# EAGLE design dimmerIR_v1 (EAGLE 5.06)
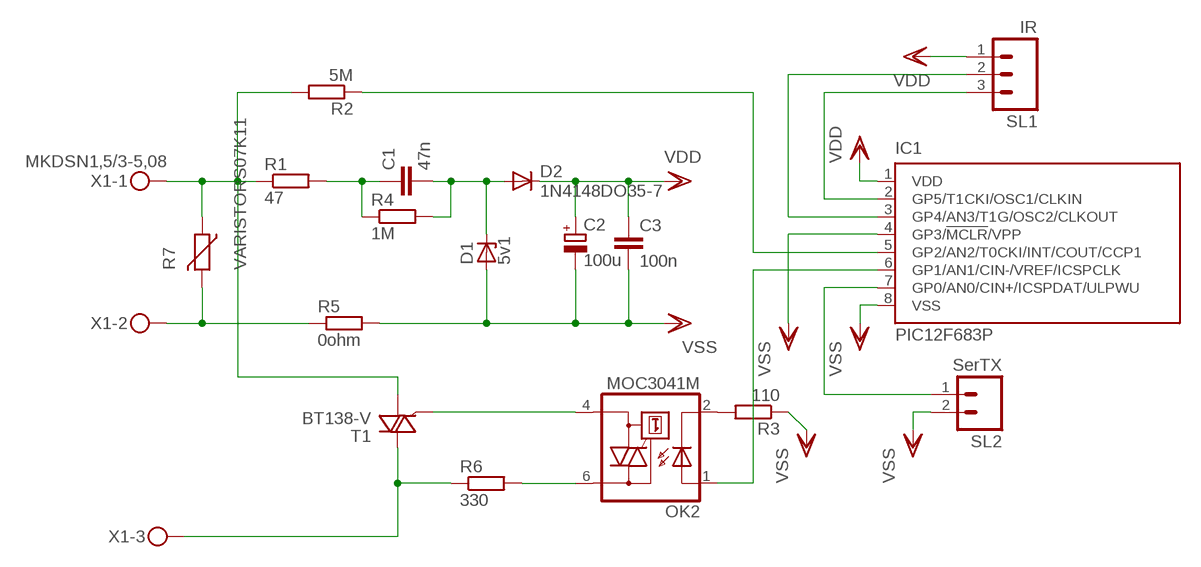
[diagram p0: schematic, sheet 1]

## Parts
C1  47n  C-EU150-054X183  [C150-054X183]
C2  100u  CPOL-EUE2.5-6  [E2,5-6]
C3  100n  C-EU050-025X075  [C050-025X075]
D1  5v1  ZENER-DIODEDO34-7  [DO34Z7]
D2  1N4148DO35-7  [DO35-7]
IC1  PIC12F683P  [DIL8]
OK2  MOC3041M  [DIL06]
R1  47  R-EU_0204/7  [0204/7]
R2  5M  R-EU_0207/10  [0207/10]
R3  110  R-EU_0207/10  [0207/10]
R4  1M  R-EU_M1206  [M1206]
R5  0ohm  R-EU_M1206  [M1206]
R6  330  R-EU_0207/10  [0207/10]
R7  VARISTORS07K11  [S07K11]
SL1  IR  M03  [03P]
SL2  SerTX  M02  [02P]
T1  BT138-V  [TO220BV]
X1  MKDSN1,5/3-5,08  [MKDSN1,5/3-5,08]

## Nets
N$1: R1.1 R2.2 R7.1 T1.T1(A1) X1.1
N$2: C1.2 D1.C D2.A R4.2
N$3: C1.1 R1.2 R4.1
N$4: R6.1 T1.T2(A2) X1.3
N$5: OK2.6(A2) R6.2
N$6: OK2.4(A1) T1.G
N$7: IC1.5(GP2/AN2/T0CKI/INT/COUT/CCP1) R2.1
N$8: IC1.6(GP1/AN1/CIN-/VREF/ICSPCLK) OK2.1(A)
N$9: OK2.2(C) R3.2
N$10: IC1.3(GP4/AN3/T1G/OSC2/CLKOUT) SL1.2
N$11: IC1.2(GP5/T1CKI/OSC1/CLKIN) SL1.3
N$13: R5.1 R7.2 X1.2
N$15: IC1.7(GP0/AN0/CIN+/ICSPDAT/ULPWU) SL2.1
VDD: C2.+ C3.1 D2.C IC1.1(VDD) SL1.1
VSS: C2.- C3.2 D1.A IC1.4(GP3/!MCLR!/VPP) IC1.8(VSS) R3.1 R5.2 SL2.2

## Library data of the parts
C1 C3 = rcl:C-EU: CAPACITOR, European symbol
C2 = rcl:CPOL-EU: POLARIZED CAPACITOR, European symbol
D1 = diode:ZENER-DIODE: Z-Diode
D2 = diode:1N4148: DIODE
IC1 = microchip:PIC12F683: 8-Pin Flash-Based, 8-Bit CMOS Microcontrollers with nanoWatt Technology Source: http://ww1.microchip.com/downloads/en/DeviceDoc/41211D_.pdf
OK2 = optocoupler:MOC30*: 6-Pin DIP Zero-Cross Optoisolators Triac Driver Output (250/400 Volt Peak) Source: http://www.fairchildsemi.com/ds/MO/MOC3043-M.pdf
R1-R6 = rcl:R-EU_: RESISTOR, European symbol
R7 = varistor:VARISTOR: VARISTOR
SL1 = con-amp-quick:M03: AMP QUICK CONNECTOR
SL2 = con-amp-quick:M02: AMP QUICK CONNECTOR
T1 = triac:BT138: TRIAC Source: http://www.semiconductors.philips.com BT138_SERIES_2.pdf
X1 = con-phoenix-508:MKDSN1,5/3-5,08: MKDSN 1,5/ 3-5,08 Printklemme Nennstrom: 13,5 A Nennspannung: 250 V Rastermaß: 5,08 mm Polzahl: 3 Anschlussart: Schraubanschluss Montage: Löten Anschlussrichtung Leiter/Platine: 0 ° Artikelnummer: 1729131 Source: http://eshop.phoenixcontact.com .. 1729131.pdf

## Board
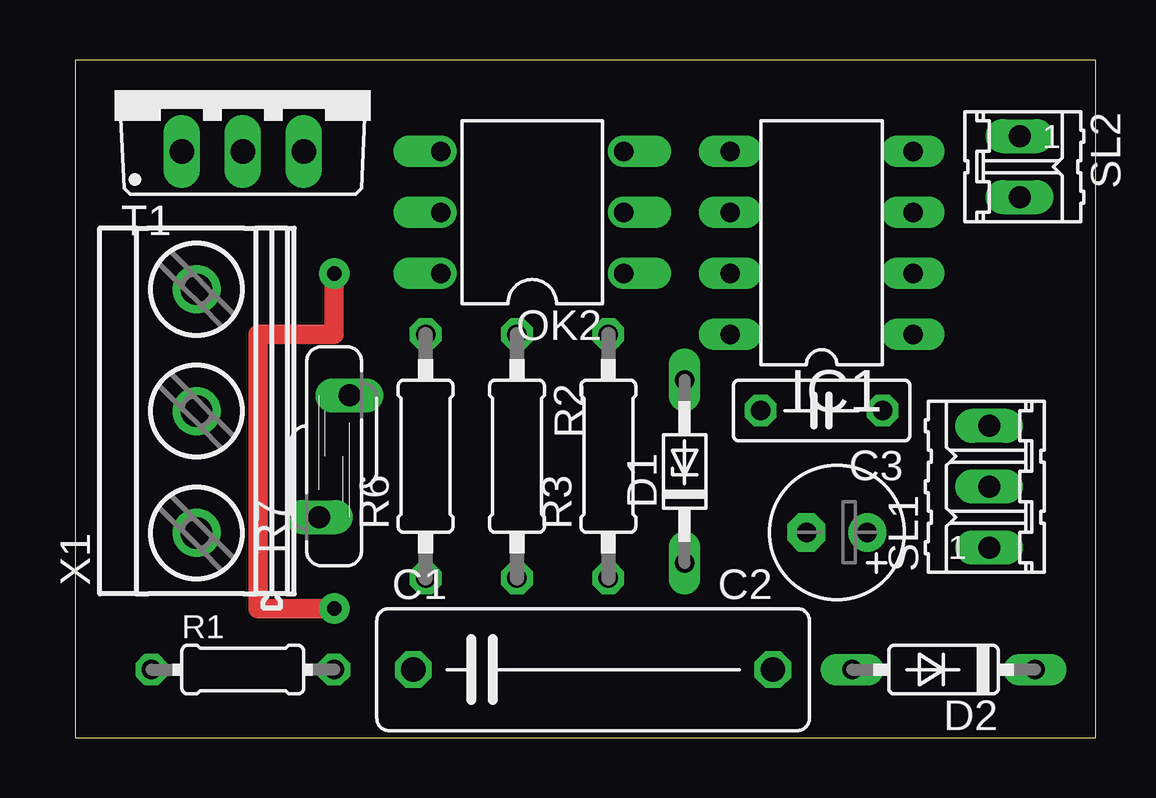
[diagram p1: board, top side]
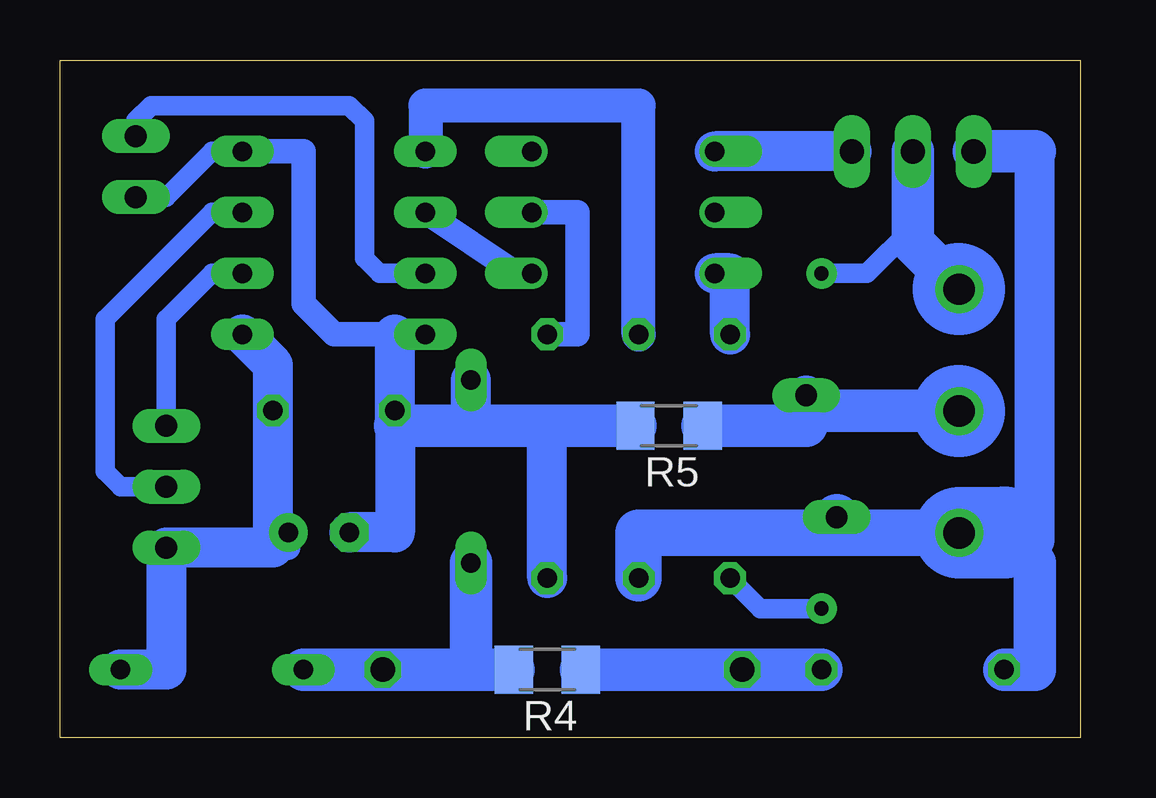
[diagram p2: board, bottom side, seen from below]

Size 42.54 x 28.24 mm. Coordinates in mm from the lower left corner, seen from the top.
Outline: 0,28.24 0,0 42.54,0 42.54,28.24 0,28.24
Copper layers (1*16): Top 0.035mm / dielectric 1.5mm / Bottom 0.035mm
Design rules "default": minimum track width 10mil, minimum drill 24mil, track to track 8mil, track to pad 8mil, pad to pad 8mil, via to via 8mil, smd to smd 8mil, copper to edge 40mil, drill to drill 8mil, minimum pad ring 10mil, minimum via ring 8mil, stop-mask expansion 4mil, vias tented up to drill 0mil, thermal gap 10mil

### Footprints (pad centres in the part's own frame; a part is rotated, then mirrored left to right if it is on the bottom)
C150-054X183 = drill 1.016 octagon: 1 -7.493,0; 2 7.493,0
E2,5-6 = drill 0.813 pad 1.6 round: + -1.27,0 | drill 0.813 pad 1.6 octagon: - 1.27,0
C050-025X075 = drill 0.813 octagon: 1 -2.54,0; 2 2.54,0
DO34Z7 = drill 0.813 long: A 3.81,0; C -3.81,0
DO35-7 = drill 0.813 long: A 3.81,0; C -3.81,0
DIL8 = drill 0.813 long: 1 -3.81,-3.81; 2 -1.27,-3.81; 3 1.27,-3.81; 4 3.81,-3.81; 5 3.81,3.81; 6 1.27,3.81; 7 -1.27,3.81; 8 -3.81,3.81
DIL06 = drill 0.813 offset: 1 -2.54,-3.81; 2 0,-3.81; 3 2.54,-3.81; 4 2.54,3.81; 5 0,3.81; 6 -2.54,3.81
0204/7 = drill 0.813 octagon: 1 -3.81,0; 2 3.81,0
0207/10 = drill 0.813 octagon: 1 -5.08,0; 2 5.08,0
M1206 = smd 1.6 x 2: 1 -1.4,0; 2 1.4,0
S07K11 = drill 0.914 long: 1 -0.635,-2.54; 2 0.635,2.54
03P = drill 0.914 long: 1 -2.54,0; 2 0,0; 3 2.54,0
02P = drill 0.914 long: 1 -1.27,0; 2 1.27,0
TO220BV = drill 1.016 long: G 2.54,-2.54; T1 -2.54,-2.54; T2 0,-2.54
MKDSN1,5/3-5,08 = drill 1.3 pad 2 round: 1 -7.641,0.025; 2 -2.561,0.025; 3 2.519,0.025

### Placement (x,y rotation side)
C1  21.59,2.85 0 top
C2  31.75,8.56 180 top
C3  31.12,13.64 180 top
D1  25.4,11.1 90 top
D2  36.2,2.85 180 top
IC1  31.12,20.62 90 top
OK2  19.05,21.9 90 top
R1  6.98,2.85 0 top
R2  18.41,11.73 270 top
R3  22.23,11.73 90 top
R4  22.23,2.85 180 bottom
R5  17.15,13 180 bottom
R6  14.61,11.73 90 top
R7  10.8,11.73 0 top
SL1  38.1,10.46 90 top
SL2  39.37,23.8 270 top
T1  6.98,26.98 0 top
X1  5.08,16.18 90 top

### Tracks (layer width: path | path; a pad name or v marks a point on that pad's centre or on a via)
N$1
  Bottom 1.27: 3.18,8.56 1.91,8.56 1.91,8.23 1.91,7.29
  Bottom 1.676: 1.91,8.23 1.91,24.44
  Bottom 1.778: R1.1 1.91,2.85 1.91,7.29 | 1.91,24.44 T1.T1
  Bottom 1.93: X1.1 10.16,8.54 | 10.16,8.54 14.61,8.54 18.41,8.54 R2.2 | 10.16,8.54 R7.1
  Bottom 3.81: X1.1 3.18,8.54 3.18,8.56
N$2
  Bottom 1.778: D2.A C1.2 25.4,2.85 | 25.4,2.85 D1.C | R4.2 25.4,2.85
N$3
  Bottom 1.422: 12.7,2.85 C1.1
  Bottom 1.778: R1.2 12.7,2.85 R4.1
N$4  (via drill 0.6 pad 1.27)
  Top 0.813: v10.8,5.39 7.62,5.39 7.62,16.82 10.8,16.82 v10.8,19.36
  Bottom 0.813: R6.1 13.34,5.39 v10.8,5.39 | v10.8,19.36 8.89,19.36 6.98,21.26
  Bottom 1.778: 5.08,18.72 6.98,20.62 6.98,21.26 T1.T2
  Bottom 3.81: X1.3 5.08,18.7 5.08,18.72
N$5
  Bottom 1.676: OK2.6 14.61,19.36 R6.2
N$6
  Bottom 1.676: T1.G OK2.4
N$7
  Bottom 1.422: IC1.5 27.3,26.34 18.41,26.34 R2.1
N$8
  Bottom 1.016: OK2.1 23.5,19.36 IC1.6
N$9
  Bottom 1.016: OK2.2 20.95,21.9 20.95,16.82 R3.2
N$10
  Bottom 0.813: IC1.3 36.2,21.9 40.64,17.45 40.64,11.1 40.01,10.46 SL1.2
N$11
  Bottom 0.813: IC1.2 36.2,19.36 38.1,17.45 SL1.3
N$13
  Bottom 1.676: 11.43,13 R7.2
  Bottom 1.778: R5.1 11.43,13 11.43,13.64 5.08,13.64
  Bottom 3.81: X1.2 5.08,13.62 5.08,13.64
N$14  (via drill 0.6 pad 1.27)
  other vias: 10.8,5.39
N$15
  Bottom 0.813: IC1.7 29.21,19.36 29.84,19.99 29.84,25.7 30.48,26.34 38.74,26.34 39.37,25.7 SL2.1
N$16  (via drill 0.6 pad 1.27)
  other vias: 10.8,19.36
VDD
  Bottom 1.016: C2.+ 33.02,7.93 33.66,7.93
  Bottom 1.676: D2.C 38.1,2.85 SL1.1 33.66,7.93 C3.1 33.66,15.55 IC1.1
VSS
  Bottom 0.813: IC1.4 36.2,24.44 38.1,22.53 SL2.2
  Bottom 1.016: 28.58,16.82 IC1.8 31.12,16.82 32.38,18.09 32.38,24.44 IC1.4
  Bottom 1.676: C2.- 28.58,8.56 28.58,13 C3.2 28.58,16.82 | 25.4,13 D1.A | R3.1 22.23,13
  Bottom 1.778: R5.2 22.23,13 25.4,13 28.58,13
